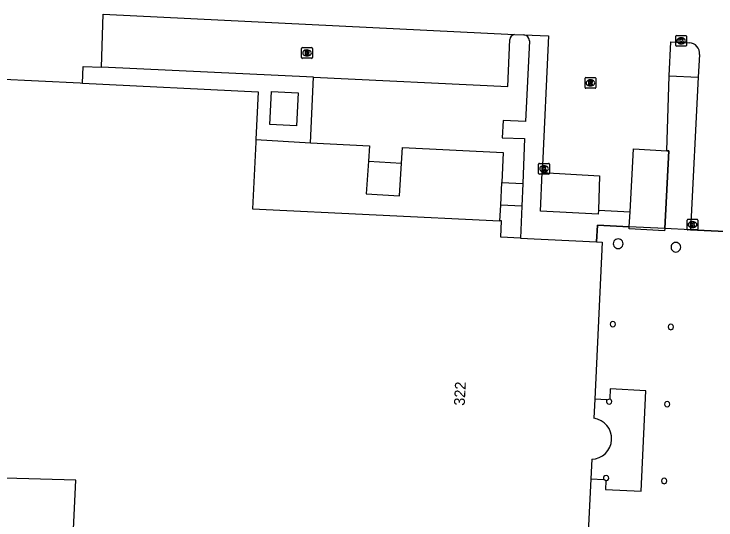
# Model space of a CAD drawing. Extents: x 161094 to 161705, y 379509 to 380907.
# Drawn here: x 161388.6 to 161453.8, y 379714.9 to 379761.9 of the extents above; entities that cross this region are included whole.
import ezdxf

# ---------------------------------------------------------------- set-up
doc = ezdxf.new("R2010")
doc.units = 0
for name, color, linetype in [('IMGEO_Hek', 7, 'Continuous'), ('IMGEO_Kolk', 7, 'Continuous'), ('IMGEO_Lage_trafo', 7, 'Continuous'), ('IMGEO_Pand', 7, 'Continuous'), ('IMGEO_Pand_nummerreeks', 7, 'Continuous'), ('IMGEO_Pand_overbouw', 7, 'Continuous'), ('IMGEO_Parkeervlak_open', 7, 'Continuous'), ('IMGEO_Rijbaan_lokaal_gesloten', 7, 'Continuous'), ('IMGEO_Rioolput', 7, 'Continuous'), ('IMGEO_Voetpad_gesloten', 7, 'Continuous'), ('IMGEO_Voetpad_open', 7, 'Continuous')]:
    doc.layers.add(name, color=color, linetype=linetype)

msp = doc.modelspace()

# ---------------------------------------------------------------- linework, layer by layer
at = {"layer": 'IMGEO_Hek'}
for points in [[(161445.824, 379743.532), (161446.142, 379749.367), (161449.235, 379749.199)], [(161449.235, 379749.199), (161449.419, 379749.189), (161449.04, 379741.982)], [(161445.752, 379742.144), (161445.824, 379743.532)], [(161449.04, 379741.982), (161449.03, 379741.781), (161445.742, 379741.953), (161445.752, 379742.144)]]:
    msp.add_lwpolyline(points, dxfattribs=at)
at = {"layer": 'IMGEO_Kolk'}
for p, q in [((161450.064, 379758.982), (161450.064, 379759.834)), ((161450.139, 379759.908), (161450.991, 379759.908)), ((161451.065, 379759.834), (161451.065, 379758.982)), ((161450.575, 379759.128), (161450.55, 379759.128)), ((161450.552, 379759.688), (161450.577, 379759.688)), ((161450.991, 379758.908), (161450.139, 379758.908)), ((161437.4, 379748.029), (161438.252, 379748.029)), ((161437.325, 379747.103), (161437.325, 379747.955)), ((161437.813, 379747.809), (161437.838, 379747.809)), ((161438.326, 379747.955), (161438.326, 379747.103)), ((161438.252, 379747.029), (161437.4, 379747.029)), ((161437.836, 379747.249), (161437.811, 379747.249)), ((161451.123, 379741.92), (161451.123, 379742.772)), ((161451.198, 379742.846), (161452.05, 379742.846)), ((161452.124, 379742.772), (161452.124, 379741.92)), ((161451.611, 379742.626), (161451.636, 379742.626)), ((161452.05, 379741.846), (161451.198, 379741.846)), ((161451.634, 379742.066), (161451.609, 379742.066))]:
    msp.add_line(p, q, dxfattribs=at)
for points in [[(161450.064, 379758.982), (161450.064, 379759.834)], [(161450.139, 379759.908), (161450.991, 379759.908)], [(161451.065, 379759.834), (161451.065, 379758.982)], [(161450.385, 379759.608), (161450.508, 379759.608), (161450.508, 379759.457), (161450.638, 379759.608), (161450.802, 379759.608), (161450.656, 379759.457), (161450.809, 379759.208), (161450.657, 379759.208), (161450.572, 379759.372), (161450.508, 379759.305), (161450.508, 379759.208), (161450.385, 379759.208), (161450.385, 379759.608)], [(161450.991, 379758.908), (161450.139, 379758.908)], [(161437.4, 379748.029), (161438.252, 379748.029)], [(161437.325, 379747.103), (161437.325, 379747.955)], [(161437.646, 379747.729), (161437.769, 379747.729), (161437.769, 379747.578), (161437.899, 379747.729), (161438.063, 379747.729), (161437.917, 379747.578), (161438.07, 379747.329), (161437.918, 379747.329), (161437.833, 379747.493), (161437.769, 379747.426), (161437.769, 379747.329), (161437.646, 379747.329), (161437.646, 379747.729)], [(161438.326, 379747.955), (161438.326, 379747.103)], [(161438.252, 379747.029), (161437.4, 379747.029)], [(161451.123, 379741.92), (161451.123, 379742.772)], [(161451.198, 379742.846), (161452.05, 379742.846)], [(161452.124, 379742.772), (161452.124, 379741.92)], [(161451.444, 379742.546), (161451.567, 379742.546), (161451.567, 379742.395), (161451.697, 379742.546), (161451.861, 379742.546), (161451.715, 379742.395), (161451.868, 379742.146), (161451.716, 379742.146), (161451.631, 379742.31), (161451.567, 379742.243), (161451.567, 379742.146), (161451.444, 379742.146), (161451.444, 379742.546)], [(161452.05, 379741.846), (161451.198, 379741.846)]]:
    msp.add_lwpolyline(points, dxfattribs=at)
for centre, start, end in [((161450.141, 379759.832), 91.55205, 178.44795), ((161450.141, 379759.832), 91.55205, 178.44795), ((161450.989, 379759.832), 1.55205, 88.44795), ((161450.989, 379759.832), 1.55205, 88.44795), ((161450.141, 379758.984), 181.55205, 268.44795), ((161450.141, 379758.984), 181.55205, 268.44795), ((161450.989, 379758.984), 271.55205, 358.44795), ((161450.989, 379758.984), 271.55205, 358.44795), ((161437.402, 379747.953), 91.55205, 178.44795), ((161437.402, 379747.953), 91.55205, 178.44795), ((161438.25, 379747.953), 1.55205, 88.44795), ((161438.25, 379747.953), 1.55205, 88.44795), ((161437.402, 379747.105), 181.55205, 268.44795), ((161437.402, 379747.105), 181.55205, 268.44795), ((161438.25, 379747.105), 271.55205, 358.44795), ((161438.25, 379747.105), 271.55205, 358.44795), ((161451.2, 379742.77), 91.55205, 178.44795), ((161451.2, 379742.77), 91.55205, 178.44795), ((161452.048, 379742.77), 1.55205, 88.44795), ((161452.048, 379742.77), 1.55205, 88.44795), ((161451.2, 379741.922), 181.55205, 268.44795), ((161451.2, 379741.922), 181.55205, 268.44795), ((161452.048, 379741.922), 271.55205, 358.44795), ((161452.048, 379741.922), 271.55205, 358.44795)]:
    msp.add_arc(centre, 0.0765, start, end, dxfattribs=at)
for centre, major_axis, ratio, start_param, end_param in [((161450.551, 379759.408), (-0.387, 0.002), 0.722429, 4.712389, 7.853982), ((161450.576, 379759.408), (-0.39, 0.002), 0.717154, 1.570796, 4.712389), ((161437.812, 379747.529), (-0.387, 0.002), 0.722429, 4.712389, 7.853982), ((161437.837, 379747.529), (-0.39, 0.002), 0.717154, 1.570796, 4.712389), ((161451.61, 379742.346), (-0.387, 0.002), 0.722429, 4.712389, 7.853982), ((161451.635, 379742.346), (-0.39, 0.002), 0.717154, 1.570796, 4.712389)]:
    msp.add_ellipse(centre, major_axis=major_axis, ratio=ratio, start_param=start_param, end_param=end_param, dxfattribs=at)
at = {"layer": 'IMGEO_Lage_trafo'}
msp.add_lwpolyline([(161412.49, 379754.691), (161414.976, 379754.567), (161414.825, 379751.52), (161412.338, 379751.644), (161412.49, 379754.691)], dxfattribs=at)
at = {"layer": 'IMGEO_Pand'}
for points in [[(161386.824, 379755.883), (161386.953, 379755.876), (161394.714, 379755.496), (161394.932, 379755.485)], [(161394.932, 379755.485), (161411.276, 379754.683), (161411.058, 379750.236)], [(161411.058, 379750.236), (161411.046, 379750), (161410.743, 379743.807), (161433.729, 379742.702)], [(161435.636, 379741.089), (161433.806, 379741.181), (161433.864, 379742.696), (161433.729, 379742.702)], [(161435.636, 379741.089), (161442.709, 379740.733)], [(161442.709, 379740.733), (161443.22, 379740.706), (161442.537, 379726.14)], [(161442.537, 379726.14), (161442.449, 379724.367)], [(161443.663, 379726.071), (161443.94, 379726.177)], [(161393.342, 379697.826), (161394.323, 379718.608), (161387.744, 379718.815), (161387.652, 379717.177), (161387.093, 379717.207), (161387.165, 379718.859), (161353.985, 379720.484), (161353.912, 379718.998), (161353.33, 379719.026), (161353.409, 379720.658), (161352.052, 379720.725), (161350.399, 379720.806), (161349.468, 379701.796)], [(161442.261, 379720.561), (161442.171, 379718.753)], [(161442.171, 379718.753), (161441.094, 379697.013)], [(161443.57, 379718.564), (161443.371, 379718.693)]]:
    msp.add_lwpolyline(points, dxfattribs=at)
for centre, radius, start, end in [((161444.716, 379740.571), 0.45, 119.97301, 240.02699), ((161444.717, 379740.572), 0.449, 359.89963, 120.191), ((161444.716, 379740.571), 0.45, 240.00001, 0.03673), ((161450.076, 379740.247), 0.45, 119.97301, 240.02699), ((161450.076, 379740.247), 0.45, 0.09067, 119.99996), ((161450.076, 379740.248), 0.45, 240.00001, 0.03673), ((161444.217, 379733.109), 0.25, 119.99835, 240.00165), ((161444.217, 379733.109), 0.25, 0.11618, 119.99993), ((161444.217, 379733.109), 0.25, 240.00006, 0.11301), ((161449.622, 379732.84), 0.25, 119.99835, 240.00165), ((161449.623, 379732.842), 0.249, 359.7724, 120.34371), ((161449.622, 379732.84), 0.25, 240.00006, 0.11301), ((161443.872, 379725.936), 0.249, 147.03095, 240.19501), ((161443.873, 379725.937), 0.25, 240.00006, 0.11301), ((161443.874, 379725.937), 0.249, 359.97735, 74.67369), ((161449.273, 379725.665), 0.25, 119.99835, 240.00165), ((161449.273, 379725.666), 0.249, 359.62198, 120.13222), ((161449.272, 379725.664), 0.25, 240.06628, 359.95003), ((161442.199, 379722.472), 1.912, 271.87035, 82.47391), ((161443.591, 379718.813), 0.251, 119.98167, 208.53214), ((161443.59, 379718.812), 0.251, 0.23077, 119.65616), ((161443.591, 379718.813), 0.25, 265.22341, 359.93138), ((161448.986, 379718.543), 0.25, 119.99835, 240.00165), ((161448.986, 379718.543), 0.25, 359.88699, 119.99994), ((161448.987, 379718.542), 0.249, 239.65629, 0.2276)]:
    msp.add_arc(centre, radius, start, end, dxfattribs=at)
at = {"layer": 'IMGEO_Pand_overbouw'}
for points in [[(161442.795, 379742.289), (161442.709, 379740.733), (161443.22, 379740.706), (161442.537, 379726.14), (161442.449, 379724.367)], [(161460.755, 379740.055), (161460.82, 379741.402), (161459.765, 379741.454), (161459.115, 379741.486), (161451.449, 379741.864), (161449.04, 379741.982), (161445.752, 379742.144), (161442.795, 379742.289)], [(161442.261, 379720.561), (161442.171, 379718.753), (161441.094, 379697.013), (161431.78, 379697.442), (161431.696, 379695.994), (161441.029, 379695.563), (161449.168, 379695.186), (161456.81, 379694.832), (161465.062, 379694.45), (161465.67, 379694.422), (161467.944, 379740.954), (161467.337, 379740.979), (161466.381, 379741.018), (161466.333, 379739.73)]]:
    msp.add_lwpolyline(points, dxfattribs=at)
msp.add_arc((161442.199, 379722.472), 1.912, 271.87035, 82.47391, dxfattribs=at)
at = {"layer": 'IMGEO_Parkeervlak_open'}
msp.add_lwpolyline([(161449.04, 379741.982), (161449.03, 379741.781), (161445.742, 379741.953), (161445.752, 379742.144)], dxfattribs=at)
at = {"layer": 'IMGEO_Rijbaan_lokaal_gesloten'}
for points in [[(161396.715, 379756.957), (161396.874, 379761.893), (161435.089, 379759.99)], [(161435.089, 379759.99), (161435.965, 379759.96)], [(161435.965, 379759.96), (161438.228, 379759.883), (161437.657, 379747.198)], [(161449.468, 379756.157), (161449.598, 379759.302), (161451.317, 379759.209)], [(161452.284, 379758.132), (161452.159, 379756.027)], [(161394.932, 379755.485), (161395.008, 379757.039), (161396.715, 379756.957)], [(161449.235, 379749.199), (161449.468, 379756.157)], [(161452.159, 379756.027), (161451.449, 379741.864)], [(161445.824, 379743.532), (161446.142, 379749.367), (161449.235, 379749.199)], [(161437.657, 379747.198), (161442.991, 379746.88), (161442.878, 379743.692)], [(161442.878, 379743.692), (161445.824, 379743.532)], [(161451.449, 379741.864), (161459.115, 379741.486)]]:
    msp.add_lwpolyline(points, dxfattribs=at)
msp.add_arc((161451.312, 379758.232), 0.977, 354.11095, 89.72813, dxfattribs=at)
at = {"layer": 'IMGEO_Rioolput'}
for p, q in [((161415.302, 379757.856), (161415.302, 379758.708)), ((161415.377, 379758.782), (161416.229, 379758.782)), ((161415.79, 379758.562), (161415.815, 379758.562)), ((161416.303, 379758.708), (161416.303, 379757.856)), ((161416.229, 379757.782), (161415.377, 379757.782)), ((161415.813, 379758.002), (161415.788, 379758.002)), ((161441.637, 379755.077), (161441.637, 379755.929)), ((161441.712, 379756.003), (161442.564, 379756.003)), ((161442.638, 379755.929), (161442.638, 379755.077)), ((161442.148, 379755.223), (161442.123, 379755.223)), ((161442.125, 379755.783), (161442.15, 379755.783)), ((161442.564, 379755.003), (161441.712, 379755.003))]:
    msp.add_line(p, q, dxfattribs=at)
for points in [[(161415.302, 379757.856), (161415.302, 379758.708)], [(161415.377, 379758.782), (161416.229, 379758.782)], [(161415.891, 379758.48), (161415.639, 379758.482), (161415.639, 379758.082)], [(161415.817, 379758.401), (161415.763, 379758.401), (161415.763, 379758.32)], [(161416.303, 379758.708), (161416.303, 379757.856)], [(161416.229, 379757.782), (161415.377, 379757.782)], [(161415.639, 379758.082), (161415.763, 379758.082), (161415.763, 379758.244), (161415.774, 379758.244)], [(161415.763, 379758.32), (161415.815, 379758.32)], [(161415.821, 379758.215), (161415.892, 379758.082), (161416.032, 379758.082), (161415.967, 379758.208)], [(161441.637, 379755.077), (161441.637, 379755.929)], [(161441.712, 379756.003), (161442.564, 379756.003)], [(161442.638, 379755.929), (161442.638, 379755.077)], [(161442.226, 379755.701), (161441.974, 379755.703), (161441.974, 379755.303)], [(161441.974, 379755.303), (161442.098, 379755.303), (161442.098, 379755.465), (161442.109, 379755.465)], [(161442.152, 379755.622), (161442.098, 379755.622), (161442.098, 379755.541)], [(161442.098, 379755.541), (161442.15, 379755.541)], [(161442.156, 379755.436), (161442.227, 379755.303), (161442.367, 379755.303), (161442.302, 379755.429)], [(161442.564, 379755.003), (161441.712, 379755.003)]]:
    msp.add_lwpolyline(points, dxfattribs=at)
for centre, radius, start, end in [((161415.379, 379758.706), 0.0765, 91.55205, 178.44795), ((161415.379, 379758.706), 0.0765, 91.55205, 178.44795), ((161415.823, 379758.305), 0.0964, 77.00612, 93.18647), ((161415.837, 379758.362), 0.0378, 276.66336, 79.67722), ((161415.89, 379758.37), 0.109, 350.36119, 89.41601), ((161416.227, 379758.706), 0.0765, 1.55205, 88.44795), ((161416.227, 379758.706), 0.0765, 1.55205, 88.44795), ((161415.379, 379757.858), 0.0765, 181.55205, 268.44795), ((161415.379, 379757.858), 0.0765, 181.55205, 268.44795), ((161415.773, 379758.191), 0.0533, 26.02933, 88.69889), ((161415.799, 379758.509), 0.19, 274.7715, 282.96867), ((161415.888, 379758.37), 0.112, 277.58423, 350.98172), ((161415.872, 379758.155), 0.108, 29.51342, 73.79051), ((161416.227, 379757.858), 0.0765, 271.55205, 358.44795), ((161416.227, 379757.858), 0.0765, 271.55205, 358.44795), ((161441.714, 379755.927), 0.0765, 91.55205, 178.44795), ((161441.714, 379755.927), 0.0765, 91.55205, 178.44795), ((161442.562, 379755.927), 0.0765, 1.55205, 88.44795), ((161442.562, 379755.927), 0.0765, 1.55205, 88.44795), ((161442.108, 379755.412), 0.0533, 26.02933, 88.69889), ((161442.134, 379755.73), 0.19, 274.7715, 282.96867), ((161442.158, 379755.526), 0.0964, 77.00612, 93.18647), ((161442.172, 379755.583), 0.0378, 276.66336, 79.67722), ((161442.225, 379755.591), 0.109, 350.36119, 89.41601), ((161442.223, 379755.591), 0.112, 277.58423, 350.98172), ((161442.207, 379755.376), 0.108, 29.51342, 73.79051), ((161441.714, 379755.079), 0.0765, 181.55205, 268.44795), ((161441.714, 379755.079), 0.0765, 181.55205, 268.44795), ((161442.562, 379755.079), 0.0765, 271.55205, 358.44795), ((161442.562, 379755.079), 0.0765, 271.55205, 358.44795)]:
    msp.add_arc(centre, radius, start, end, dxfattribs=at)
for centre, major_axis, ratio, start_param, end_param in [((161415.789, 379758.282), (-0.387, 0.002), 0.722429, 4.712389, 7.853982), ((161415.814, 379758.282), (-0.39, 0.002), 0.717154, 1.570796, 4.712389), ((161442.124, 379755.503), (-0.387, 0.002), 0.722429, 4.712389, 7.853982), ((161442.149, 379755.503), (-0.39, 0.002), 0.717154, 1.570796, 4.712389)]:
    msp.add_ellipse(centre, major_axis=major_axis, ratio=ratio, start_param=start_param, end_param=end_param, dxfattribs=at)
at = {"layer": 'IMGEO_Voetpad_gesloten'}
for points in [[(161416.396, 379756.022), (161396.715, 379756.957)], [(161416.137, 379749.952), (161416.396, 379756.022)], [(161411.058, 379750.236), (161416.137, 379749.952)]]:
    msp.add_lwpolyline(points, dxfattribs=at)
at = {"layer": 'IMGEO_Voetpad_open'}
for points in [[(161416.396, 379756.022), (161434.456, 379755.166), (161434.643, 379759.524)], [(161436.462, 379759.406), (161436.102, 379751.931), (161434.024, 379752.011), (161433.946, 379750.387), (161436.025, 379750.33), (161435.849, 379746.157)], [(161449.468, 379756.157), (161452.159, 379756.027)], [(161416.137, 379749.952), (161421.608, 379749.645), (161421.514, 379748.238)], [(161424.588, 379748.036), (161424.682, 379749.493), (161434.019, 379749.044), (161433.912, 379746.249)], [(161449.04, 379741.982), (161449.419, 379749.189), (161449.235, 379749.199)], [(161421.514, 379748.238), (161421.31, 379745.208), (161424.393, 379745.011), (161424.588, 379748.036)], [(161421.514, 379748.238), (161424.588, 379748.036)], [(161442.878, 379743.692), (161442.865, 379743.325), (161437.498, 379743.586), (161437.657, 379747.198)], [(161433.808, 379744.163), (161433.912, 379746.249)], [(161433.912, 379746.249), (161435.849, 379746.157)], [(161435.849, 379746.157), (161435.761, 379744.07)], [(161433.729, 379742.702), (161433.808, 379744.163)], [(161435.761, 379744.07), (161433.808, 379744.163)], [(161435.761, 379744.07), (161435.636, 379741.089)], [(161445.752, 379742.144), (161445.824, 379743.532)], [(161442.709, 379740.733), (161442.795, 379742.289), (161445.752, 379742.144)], [(161451.449, 379741.864), (161449.04, 379741.982)], [(161443.57, 379718.564), (161443.531, 379717.764), (161446.847, 379717.599), (161447.301, 379726.922), (161443.986, 379727.11), (161443.94, 379726.177)], [(161443.663, 379726.071), (161442.537, 379726.14)], [(161442.171, 379718.753), (161443.371, 379718.693)]]:
    msp.add_lwpolyline(points, dxfattribs=at)
for centre, radius, start, end in [((161435.127, 379759.507), 0.484, 94.48379, 178.02878), ((161435.921, 379759.421), 0.541, 358.42308, 85.36823)]:
    msp.add_arc(centre, radius, start, end, dxfattribs=at)

# ---------------------------------------------------------------- texts
at = {"layer": 'IMGEO_Pand_nummerreeks'}
msp.add_text('322', height=1, rotation=87.12969, dxfattribs=at).set_placement((161430.454, 379725.509))

doc.saveas('drawing.dxf')
